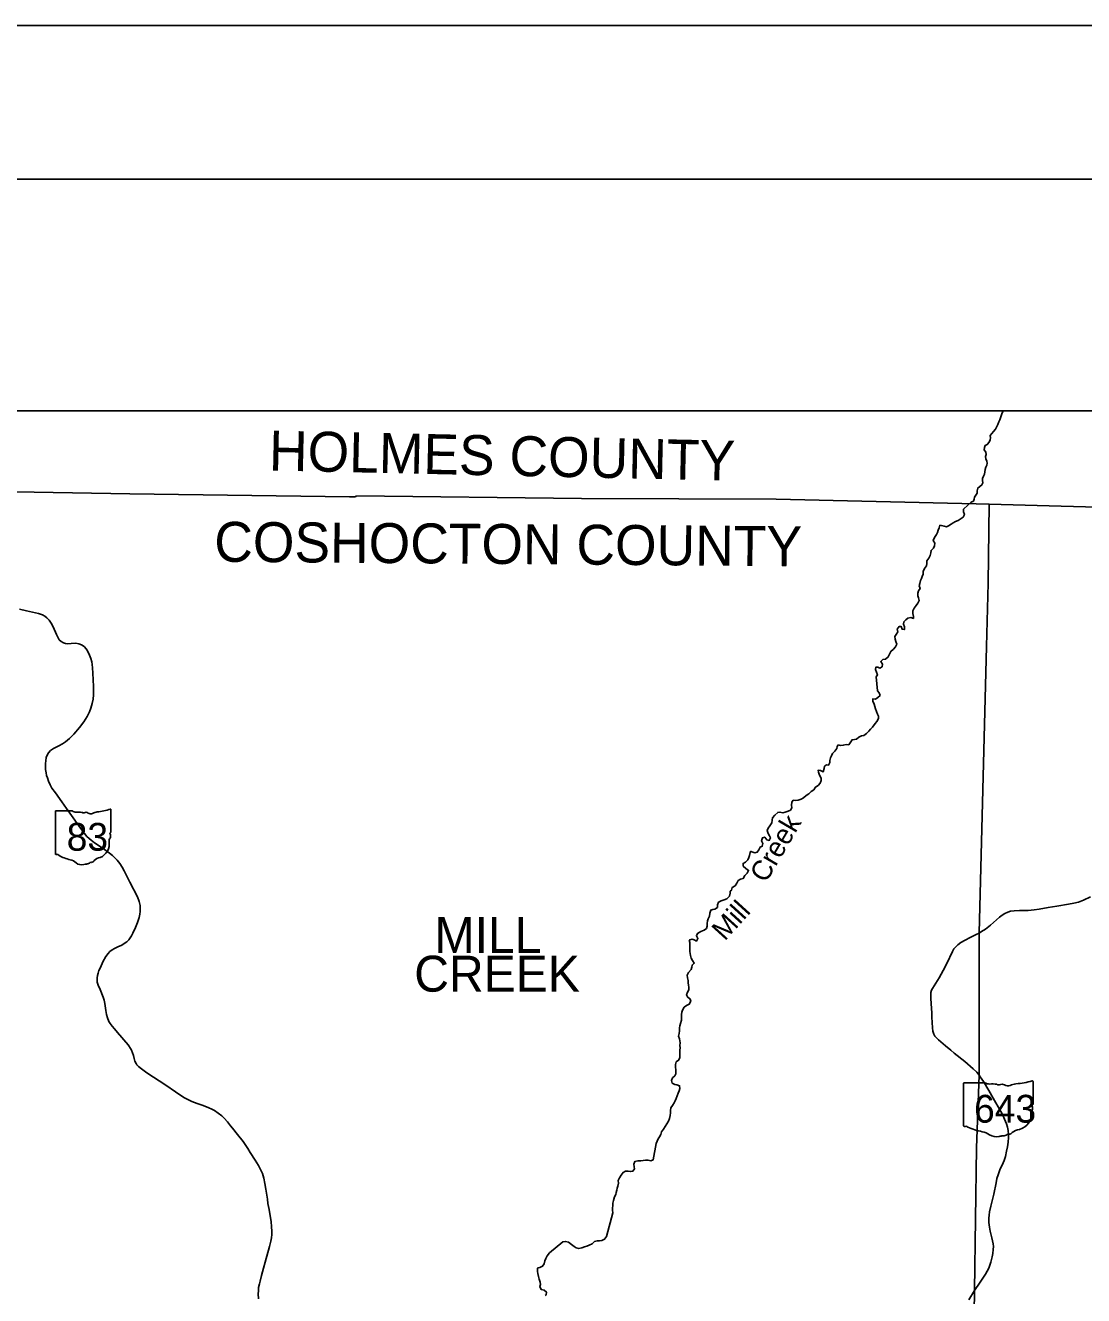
# Model space of a CAD drawing. Extents: x -6.3 to 34, y 0 to 22.
# Drawn here: x 5.581 to 9.018, y 17.873 to 22 of the extents above; entities that cross this region are included whole.
import ezdxf

# ---------------------------------------------------------------- set-up
doc = ezdxf.new("R2010")
doc.units = 0
for name, color, linetype in [('GM_X_County', 7, 'Continuous'), ('GM_X_County_Text', 7, 'Continuous'), ('GM_X_Minor_River', 7, 'Continuous'), ('GM_X_Minor_River_Text', 7, 'Continuous'), ('GM_X_State_Location', 7, 'Continuous'), ('GM_X_State_Route', 7, 'Continuous'), ('GM_X_State_Shield', 7, 'Continuous'), ('GM_X_Township', 7, 'Continuous'), ('GM_X_Township_Text', 7, 'Continuous'), ('SH_Border', 7, 'Continuous'), ('SH_Cut_Line', 7, 'Continuous'), ('SH_Text', 7, 'Continuous')]:
    doc.layers.add(name, color=color, linetype=linetype)

msp = doc.modelspace()

# ---------------------------------------------------------------- linework, layer by layer
at = {"layer": 'GM_X_County'}
for points in [[(5.4835, 20.4857), (5.92, 20.4781), (6.6339, 20.4679), (6.6359, 20.4682), (6.6378, 20.4682), (6.6401, 20.4681), (6.6424, 20.4681), (6.6467, 20.4681), (6.649, 20.4681), (6.6511, 20.4684), (6.6531, 20.4689), (6.6549, 20.4698), (6.6565, 20.4711), (7.387, 20.4633), (8.02, 20.4602), (8.6692, 20.445), (8.712, 20.4444)], [(8.712, 20.4444), (9.2192, 20.43)]]:
    msp.add_lwpolyline(points, dxfattribs=at)
at = {"layer": 'GM_X_Minor_River'}
for points in [[(8.6427, 20.4411), (8.6537, 20.4512), (8.6605, 20.454), (8.6633, 20.4605), (8.6636, 20.467), (8.6682, 20.4735), (8.6729, 20.4803), (8.6731, 20.4881), (8.6744, 20.4964), (8.6814, 20.5021), (8.6882, 20.5071), (8.6913, 20.5135), (8.6897, 20.5213), (8.6905, 20.5281), (8.6938, 20.5354), (8.6964, 20.5419), (8.6972, 20.5497), (8.6987, 20.5572), (8.7011, 20.5642), (8.7037, 20.5707), (8.7052, 20.5772), (8.7044, 20.5842), (8.7005, 20.5917), (8.7, 20.5993), (8.7023, 20.6058), (8.7008, 20.613), (8.6958, 20.6208), (8.6969, 20.6281), (8.6984, 20.6348), (8.7057, 20.6382), (8.7119, 20.6458), (8.7152, 20.6538), (8.7158, 20.6603), (8.7145, 20.6671), (8.7199, 20.6743), (8.7261, 20.6808), (8.7318, 20.6881), (8.7365, 20.6964), (8.7401, 20.7037), (8.7434, 20.7118), (8.7466, 20.7185), (8.7489, 20.725), (8.7502, 20.7318), (8.7528, 20.7383), (8.7561, 20.7455), (8.7583, 20.7482)], [(8.5514, 20.3766), (8.5568, 20.3748), (8.5657, 20.3728), (8.573, 20.3713), (8.58, 20.3739), (8.588, 20.3794), (8.595, 20.3839), (8.6025, 20.3881), (8.611, 20.3918), (8.6209, 20.3979), (8.6276, 20.4023), (8.6312, 20.4104), (8.6283, 20.419), (8.6287, 20.4284), (8.6427, 20.4411)], [(8.2214, 19.6628), (8.2289, 19.6601), (8.2374, 19.6612), (8.247, 19.6631), (8.2556, 19.6623), (8.2623, 19.6717), (8.2664, 19.6788), (8.274, 19.6799), (8.281, 19.6805), (8.2882, 19.687), (8.297, 19.6912), (8.3045, 19.6931), (8.3136, 19.6994), (8.3213, 19.7065), (8.3262, 19.713), (8.3322, 19.7196), (8.3412, 19.7313), (8.3463, 19.7381), (8.352, 19.7478), (8.3519, 19.7551), (8.349, 19.7616), (8.3454, 19.7702), (8.3424, 19.7795), (8.34, 19.7871), (8.3379, 19.7941), (8.3337, 19.804), (8.3336, 19.8118), (8.3425, 19.8108), (8.3497, 19.8163), (8.3572, 19.8224), (8.3548, 19.8315), (8.3491, 19.8382), (8.3446, 19.883), (8.3487, 19.8901), (8.3461, 19.8989), (8.3419, 19.9072), (8.3439, 19.9148), (8.3504, 19.9146), (8.3569, 19.912), (8.3639, 19.9159), (8.3654, 19.9243), (8.3594, 19.9334), (8.3663, 19.9402), (8.3754, 19.9408), (8.3839, 19.9481), (8.3875, 19.9575), (8.3924, 19.9661), (8.4009, 19.973), (8.4079, 19.9805), (8.4112, 19.9899), (8.4083, 19.9977), (8.4059, 20.0056), (8.4048, 20.0139), (8.4092, 20.0212), (8.4151, 20.0293), (8.413, 20.0379), (8.4189, 20.0468), (8.4259, 20.0466), (8.4288, 20.038), (8.4361, 20.0367), (8.4366, 20.0461), (8.4339, 20.055), (8.4344, 20.062), (8.4408, 20.0688), (8.4478, 20.0743), (8.4567, 20.0759), (8.4658, 20.0731), (8.4662, 20.0796), (8.4641, 20.0887), (8.464, 20.0976), (8.4684, 20.107), (8.4748, 20.1151), (8.4803, 20.1222), (8.4838, 20.1313), (8.4822, 20.1404), (8.4801, 20.1469), (8.4795, 20.1553), (8.4823, 20.1631), (8.487, 20.1704), (8.4848, 20.179), (8.4866, 20.1861), (8.4889, 20.196), (8.4914, 20.2025), (8.494, 20.2093), (8.4973, 20.2174), (8.4975, 20.226), (8.5019, 20.2354), (8.5078, 20.2438), (8.509, 20.2521), (8.5092, 20.2604), (8.5162, 20.2686), (8.5195, 20.2777), (8.5221, 20.2868), (8.523, 20.2941), (8.5311, 20.3015), (8.5344, 20.3088), (8.5351, 20.3179), (8.5299, 20.3265), (8.534, 20.3359), (8.5404, 20.3456), (8.5437, 20.3524)], [(8.5437, 20.3524), (8.5465, 20.3597), (8.5491, 20.3675), (8.5514, 20.3766)], [(8.0749, 19.4824), (8.0819, 19.4818), (8.0913, 19.4829), (8.1009, 19.4859), (8.1089, 19.4901), (8.1177, 19.4977), (8.1259, 19.5032), (8.1337, 19.5105), (8.1417, 19.5166), (8.1474, 19.5249), (8.1557, 19.5299), (8.1624, 19.538), (8.1654, 19.5469), (8.1662, 19.554), (8.1609, 19.5641), (8.1575, 19.5732), (8.1561, 19.58), (8.1637, 19.5787), (8.1728, 19.5748), (8.1761, 19.5853), (8.1766, 19.5926), (8.1833, 19.597), (8.1898, 19.5968), (8.1936, 19.6052), (8.1941, 19.612), (8.1959, 19.6198), (8.1992, 19.6263), (8.2028, 19.6344), (8.2108, 19.6423), (8.2165, 19.6509), (8.2177, 19.6574), (8.2214, 19.6628)], [(7.9367, 19.3165), (7.9409, 19.3151), (7.95, 19.3112), (7.9585, 19.3141), (7.9634, 19.3209), (7.968, 19.3301), (7.9748, 19.333), (7.9765, 19.3419), (7.9721, 19.3509), (7.9749, 19.3601), (7.9826, 19.3625), (7.9895, 19.3537), (7.9975, 19.3521), (8.0011, 19.36), (7.9982, 19.3665), (7.994, 19.3748), (7.9903, 19.3836), (7.9939, 19.392), (7.9993, 19.3993), (8.0057, 19.4087), (8.0072, 19.4176), (8.0082, 19.4257), (8.0154, 19.4338), (8.0247, 19.4427), (8.0317, 19.444), (8.0414, 19.4417), (8.0492, 19.4439), (8.059, 19.4468), (8.066, 19.45), (8.0709, 19.4575), (8.0693, 19.4669), (8.0708, 19.4758), (8.0749, 19.4824)], [(7.87, 19.1868), (7.8741, 19.1897), (7.8769, 19.199), (7.8862, 19.2043), (7.8922, 19.2132), (7.896, 19.2216), (7.9043, 19.2258), (7.9126, 19.2284), (7.9177, 19.2378), (7.9257, 19.2452), (7.9301, 19.2543), (7.9209, 19.261), (7.9128, 19.2686), (7.9123, 19.2769), (7.9198, 19.2816), (7.9275, 19.2892), (7.9311, 19.2963), (7.9326, 19.3028), (7.9357, 19.3124), (7.9367, 19.3165)], [(7.7366, 19.025), (7.739, 19.0284), (7.7471, 19.0311), (7.7536, 19.029), (7.7609, 19.0246), (7.7655, 19.0333), (7.7608, 19.0418), (7.7641, 19.0497), (7.7747, 19.056), (7.7856, 19.0602), (7.7931, 19.0662), (7.7956, 19.0728), (7.7958, 19.0814), (7.7968, 19.0905), (7.7986, 19.097), (7.8035, 19.1056), (7.8047, 19.1153), (7.807, 19.1247), (7.814, 19.1278), (7.8207, 19.1289), (7.8288, 19.1342), (7.8297, 19.143), (7.8328, 19.1509), (7.8413, 19.1556), (7.8509, 19.1585), (7.86, 19.1625), (7.8677, 19.1711), (7.87, 19.1805), (7.87, 19.1868)], [(7.7094, 18.7573), (7.7122, 18.768), (7.7121, 18.7771), (7.7118, 18.7865), (7.7128, 18.7938), (7.7156, 18.8006), (7.7213, 18.81), (7.7282, 18.8158), (7.7376, 18.8203), (7.7427, 18.8294), (7.7403, 18.8364), (7.7319, 18.8431), (7.7288, 18.8499), (7.7316, 18.8583), (7.7359, 18.8664), (7.7364, 18.875), (7.7353, 18.8815), (7.7337, 18.8887), (7.7337, 18.8971), (7.732, 18.9057), (7.7309, 18.914), (7.7353, 18.9226), (7.7433, 18.932), (7.7456, 18.9401), (7.7468, 18.9467), (7.7536, 18.9529), (7.748, 18.9613), (7.7436, 18.9698), (7.7417, 18.9781), (7.7404, 18.9847), (7.7395, 18.9912), (7.739, 18.9992), (7.7392, 19.0063), (7.7394, 19.0149), (7.7393, 19.0214), (7.7366, 19.025)], [(7.7068, 18.6706), (7.7078, 18.6779), (7.7073, 18.6851), (7.708, 18.6937), (7.7069, 18.7003), (7.7053, 18.707), (7.7029, 18.7161), (7.7042, 18.7247), (7.7054, 18.7336), (7.7056, 18.7424), (7.7063, 18.749), (7.7094, 18.7573)], [(7.5307, 18.2772), (7.5385, 18.2768), (7.5455, 18.2758), (7.5546, 18.2776), (7.5592, 18.2852), (7.5582, 18.2917), (7.5571, 18.3), (7.5604, 18.3081), (7.57, 18.3103), (7.5796, 18.3111), (7.5882, 18.3119), (7.5952, 18.313), (7.604, 18.3128), (7.6126, 18.3113), (7.6204, 18.3145), (7.6302, 18.3666), (7.633, 18.3745), (7.6366, 18.3818), (7.6407, 18.3883), (7.6448, 18.3964), (7.6473, 18.405), (7.6538, 18.4134), (7.6589, 18.4218), (7.6648, 18.4309), (7.67, 18.4393), (7.6733, 18.4479), (7.6755, 18.4581), (7.6768, 18.4662), (7.677, 18.4745), (7.678, 18.4826), (7.6826, 18.4907), (7.688, 18.499), (7.6921, 18.5056), (7.6954, 18.5137), (7.6985, 18.5218), (7.701, 18.5304), (7.7046, 18.5387), (7.7072, 18.5458), (7.7061, 18.5546), (7.6975, 18.5572), (7.6907, 18.559), (7.6818, 18.5636), (7.6795, 18.5722), (7.6825, 18.58), (7.6905, 18.5868), (7.6939, 18.5934), (7.6933, 18.6004), (7.6935, 18.6077), (7.6932, 18.6142), (7.6929, 18.6238), (7.6952, 18.6319), (7.7029, 18.6377), (7.7068, 18.645), (7.707, 18.6541), (7.7069, 18.6609), (7.7066, 18.669), (7.7068, 18.6706)], [(7.2455, 17.9629), (7.2522, 17.9643), (7.261, 17.9685), (7.2656, 17.9766), (7.2684, 17.9863), (7.272, 17.9936), (7.2761, 18.0022), (7.283, 18.0114), (7.3267, 18.0481), (7.3355, 18.0492), (7.3452, 18.0461), (7.3546, 18.0394), (7.3632, 18.0322), (7.3697, 18.0278), (7.3786, 18.0258), (7.3882, 18.0279), (7.397, 18.0316), (7.4048, 18.034), (7.4123, 18.0364), (7.4216, 18.0411), (7.4296, 18.0492), (7.4387, 18.0511), (7.4452, 18.0506), (7.4535, 18.052), (7.4626, 18.0562), (7.4685, 18.0646), (7.489, 18.1418), (7.4882, 18.1504), (7.4876, 18.1574), (7.4891, 18.1658), (7.4896, 18.1733), (7.4913, 18.1819), (7.4946, 18.1937), (7.4985, 18.201), (7.5003, 18.2078), (7.5018, 18.2151), (7.5033, 18.2221), (7.5051, 18.2286), (7.5071, 18.2383), (7.507, 18.2469), (7.5108, 18.2558), (7.5165, 18.2646), (7.5222, 18.2733), (7.5307, 18.2772)], [(7.2688, 17.8729), (7.2725, 17.8753), (7.2732, 17.8845), (7.2657, 17.8902), (7.2568, 17.8924), (7.2521, 17.9021), (7.2541, 17.9086), (7.2535, 17.9169), (7.2498, 17.9265), (7.2474, 17.9351), (7.245, 17.9442), (7.2442, 17.9507), (7.2449, 17.9599), (7.2455, 17.9629)]]:
    msp.add_lwpolyline(points, dxfattribs=at)
at = {"layer": 'GM_X_State_Route'}
for points in [[(5.8139, 18.899), (5.8141, 18.905), (5.8149, 18.9126), (5.8169, 18.9206), (5.8198, 18.9291), (5.8246, 18.9393), (5.8329, 18.9574), (5.8416, 18.9743), (5.8494, 18.9849), (5.8551, 18.9909), (5.8625, 18.9964), (5.8702, 19.0005), (5.8809, 19.0056), (5.8941, 19.012), (5.9021, 19.0167), (5.9104, 19.0227), (5.9166, 19.0288), (5.921, 19.0348), (5.9258, 19.0416), (5.9301, 19.0504), (5.9382, 19.0689), (5.9445, 19.0847), (5.9505, 19.1017), (5.9528, 19.1119), (5.9539, 19.1212), (5.9539, 19.1312), (5.9537, 19.1402), (5.9505, 19.1533), (5.9445, 19.169), (5.9203, 19.2166), (5.9018, 19.2525), (5.8952, 19.265), (5.8873, 19.2768), (5.8788, 19.2875), (5.8732, 19.2936), (5.8636, 19.3029), (5.8545, 19.31), (5.8332, 19.3254), (5.8056, 19.3438), (5.8, 19.3481), (5.7947, 19.3522), (5.7882, 19.3577), (5.7807, 19.365), (5.7725, 19.3744), (5.7596, 19.3917), (5.7254, 19.4403), (5.7144, 19.4559), (5.6987, 19.4777), (5.6782, 19.5063), (5.6672, 19.5221), (5.6608, 19.533), (5.6559, 19.5446), (5.6522, 19.5549), (5.6498, 19.5625), (5.6479, 19.5718), (5.6463, 19.5825), (5.6456, 19.5891), (5.6458, 19.6013), (5.6467, 19.6107), (5.6488, 19.6208), (5.6531, 19.6307), (5.6561, 19.6361), (5.6628, 19.6442), (5.6716, 19.6503), (5.6781, 19.654), (5.6891, 19.6591), (5.7018, 19.6657), (5.7116, 19.6726), (5.7239, 19.6827), (5.7387, 19.6973), (5.7571, 19.7192), (5.7703, 19.7367), (5.7816, 19.7544), (5.7893, 19.77), (5.7936, 19.7811), (5.7982, 19.7965), (5.8011, 19.8107), (5.8024, 19.8246), (5.8019, 19.8522), (5.8001, 19.8957), (5.7992, 19.9121), (5.7977, 19.923), (5.7961, 19.9324), (5.7933, 19.9431), (5.7893, 19.9539), (5.7829, 19.9676), (5.7783, 19.9743), (5.7714, 19.9818), (5.7627, 19.9876), (5.7539, 19.9911), (5.7445, 19.9927), (5.7295, 19.9912), (5.719, 19.9904), (5.7115, 19.9912), (5.7048, 19.9935), (5.6971, 19.9981), (5.6909, 20.0038), (5.6869, 20.0102), (5.682, 20.0207), (5.6708, 20.0459), (5.6647, 20.058), (5.658, 20.0678), (5.6504, 20.0756), (5.6438, 20.0805), (5.6364, 20.0848), (5.6236, 20.0891), (5.5839, 20.0982), (5.5616, 20.1033)], [(8.6103, 19.0124), (8.6199, 19.0198), (8.6333, 19.0279), (8.6497, 19.0368), (8.6693, 19.0462), (8.6793, 19.051), (8.6872, 19.0554), (8.6994, 19.0636), (8.7156, 19.0764), (8.7448, 19.1024), (8.7539, 19.1093), (8.7625, 19.1148), (8.7718, 19.119), (8.7809, 19.1218), (8.7924, 19.1234), (8.8104, 19.1239), (8.8388, 19.1245), (8.8582, 19.1263), (8.8746, 19.1286), (8.9036, 19.1341), (8.9318, 19.1385), (8.9689, 19.1445), (8.9862, 19.1477), (9.002, 19.1514), (9.0182, 19.1576), (9.0413, 19.1689)], [(8.532, 18.7228), (8.529, 18.7317), (8.5274, 18.7424), (8.5258, 18.7775), (8.525, 18.7917), (8.5243, 18.8059), (8.522, 18.8386), (8.5217, 18.8508), (8.5227, 18.8578), (8.5248, 18.8649), (8.5278, 18.871), (8.5489, 18.9055), (8.5623, 18.9292), (8.5737, 18.952), (8.5923, 18.9914), (8.5972, 18.9993), (8.6039, 19.0064), (8.6103, 19.0124)], [(5.925, 18.6706), (5.924, 18.673), (5.9147, 18.6879), (5.8801, 18.7277), (5.87, 18.7392), (5.8622, 18.7485), (5.8564, 18.7568), (5.8521, 18.7638), (5.8471, 18.7754), (5.8441, 18.7864), (5.8419, 18.7992), (5.8384, 18.8225), (5.8368, 18.8326), (5.8339, 18.8426), (5.8233, 18.8672), (5.8171, 18.8818), (5.8142, 18.8914), (5.8139, 18.899)], [(8.5871, 18.6706), (8.5699, 18.6849), (8.5466, 18.7044), (8.5395, 18.7113), (8.5355, 18.7162), (8.532, 18.7228)], [(6.3383, 17.8622), (6.3375, 17.8788), (6.3378, 17.8883), (6.3386, 17.899), (6.3411, 17.9116), (6.3433, 17.9203), (6.3482, 17.9378), (6.3546, 17.9616), (6.3601, 17.9817), (6.3742, 18.0328), (6.378, 18.0502), (6.3799, 18.0603), (6.3812, 18.0711), (6.3816, 18.0811), (6.3807, 18.0972), (6.3789, 18.1131), (6.3724, 18.1523), (6.3689, 18.1716), (6.3669, 18.1858), (6.3615, 18.2186), (6.3585, 18.2374), (6.355, 18.2546), (6.3506, 18.2693), (6.3458, 18.2808), (6.3382, 18.2955), (6.3272, 18.3132), (6.3115, 18.3378), (6.3034, 18.3508), (6.288, 18.3736), (6.2697, 18.3966), (6.2538, 18.4164), (6.2476, 18.4246), (6.2374, 18.4371), (6.227, 18.449), (6.2188, 18.4567), (6.2075, 18.4658), (6.195, 18.4741), (6.187, 18.4784), (6.1768, 18.4832), (6.1583, 18.4903), (6.1388, 18.4969), (6.1217, 18.5032), (6.1107, 18.5085), (6.096, 18.517), (6.0686, 18.5352), (6.0375, 18.5563), (5.9758, 18.5972), (5.9576, 18.6095), (5.9483, 18.617), (5.9429, 18.6229), (5.9405, 18.6266), (5.9366, 18.6342), (5.9337, 18.6436), (5.9317, 18.6531), (5.9289, 18.6614), (5.925, 18.6706)], [(8.6458, 17.8596), (8.6642, 17.8894), (8.6681, 17.8955), (8.6779, 17.9097), (8.6893, 17.9264), (8.6997, 17.9423), (8.7056, 17.9523), (8.7101, 17.9616), (8.717, 17.9811), (8.7216, 17.9988), (8.7238, 18.01), (8.7252, 18.0226), (8.7253, 18.0326), (8.7244, 18.0406), (8.7227, 18.0505), (8.7204, 18.0604), (8.7154, 18.0821), (8.7128, 18.0953), (8.7111, 18.1106), (8.7111, 18.1241), (8.7115, 18.1346), (8.7132, 18.1447), (8.7175, 18.1636), (8.7265, 18.2025), (8.7341, 18.2394), (8.737, 18.2535), (8.7404, 18.2655), (8.7438, 18.2754), (8.7476, 18.2843), (8.7536, 18.2963), (8.7607, 18.312), (8.7647, 18.3247), (8.7681, 18.3419), (8.771, 18.3566), (8.7731, 18.3717), (8.7746, 18.387), (8.7744, 18.3968), (8.7734, 18.4089), (8.771, 18.4205), (8.7676, 18.4315), (8.7617, 18.4465), (8.7558, 18.4588), (8.7491, 18.4712), (8.7245, 18.514), (8.7102, 18.5394), (8.6932, 18.5681), (8.6829, 18.584), (8.6792, 18.5892), (8.6714, 18.599), (8.6601, 18.6097), (8.6325, 18.6335), (8.5985, 18.6611), (8.5871, 18.6706)]]:
    msp.add_lwpolyline(points, dxfattribs=at)
at = {"layer": 'GM_X_State_Shield'}
for p, q in [((5.6782, 19.4459), (5.6782, 19.3087)), ((5.7329, 19.4482), (5.68, 19.4482)), ((5.8589, 19.3799), (5.8589, 19.4516)), ((5.8589, 19.3799), (5.8589, 19.3799)), ((8.6288, 18.5622), (8.6288, 18.4251)), ((8.6971, 18.5646), (8.631, 18.5646)), ((8.8546, 18.4963), (8.8546, 18.568)), ((8.8546, 18.4963), (8.8546, 18.4963))]:
    msp.add_line(p, q, dxfattribs=at)
for centre, radius, start, end in [((5.6803, 19.4462), 0.00209, 98.1301, 188.1301), ((5.7455, 19.4642), 0.0203, 231.6195, 271.1119), ((5.7523, 19.3712), 0.0729, 80.4867, 94.9883), ((5.7688, 19.4469), 0.00586, 219.7921, 297.1024), ((5.7774, 19.431), 0.0122, 54.4667, 119.1411), ((5.7931, 19.4528), 0.0147, 233.8562, 294.8282), ((5.819, 19.4063), 0.0386, 97.3462, 120.7689), ((5.7946, 19.6352), 0.1916, 275.8445, 288.9065), ((5.8569, 19.4519), 0.00201, 351.8621, 97.738), ((5.8661, 19.3499), 0.0136, 136.8065, 186.9296), ((5.8585, 19.3746), 0.00311, 107.944, 210.337), ((5.8387, 19.3656), 0.0187, 340.033, 23.6496), ((5.8568, 19.3796), 0.00215, 289.6038, 7.7341), ((5.8053, 19.3407), 0.0479, 292.3089, 8.9858), ((5.6803, 19.3084), 0.00211, 171.9584, 258.3066), ((5.6806, 19.3225), 0.0161, 267.339, 280.6039), ((5.6839, 19.3008), 0.00581, 29.7484, 93.2717), ((5.7573, 19.424), 0.1384, 240.4129, 257.1985), ((5.716, 19.2471), 0.0433, 47.1842, 75.836), ((5.7629, 19.3001), 0.0275, 230.7004, 286.2918), ((5.7787, 19.2527), 0.0226, 85.6951, 111.2099), ((5.7808, 19.2899), 0.0146, 268.777, 315.5493), ((5.794, 19.2766), 0.00412, 65.7517, 132.6484), ((5.7922, 19.2954), 0.0155, 282.8732, 323.2771), ((5.8255, 19.2702), 0.0263, 94.4031, 142.5768)]:
    msp.add_arc(centre, radius, start, end, dxfattribs=at)
for centre, major_axis, start_param, end_param in [((8.6313, 18.5625), (0.00262, 0), 1.712693, 3.28349), ((8.7129, 18.5805), (0.0254, 0), 4.042523, 4.731795), ((8.7213, 18.4876), (0.0911, 0), 1.404758, 1.657858), ((8.742, 18.5632), (0.00732, 0), 3.836095, 5.185415), ((8.7527, 18.5474), (0.0152, 0), 0.950623, 2.079405), ((8.7724, 18.5691), (0.0183, 0), 4.081561, 5.145723), ((8.8047, 18.5227), (0.0482, 0), 1.699011, 2.107814), ((8.7742, 18.7516), (0.2395, 0), 4.814394, 5.042369), ((8.8521, 18.5683), (0.00251, 0), 6.141152, 7.989035), ((8.8541, 18.491), (0.00389, 0), 1.883978, 3.671073), ((8.8293, 18.4819), (0.0234, 0), 5.934695, 6.695948), ((8.852, 18.496), (0.00269, 0), 5.05454, 6.418171), ((8.7876, 18.4571), (0.0599, 0), 5.101752, 6.440018), ((8.8636, 18.4662), (0.017, 0), 2.387724, 3.262537), ((8.6314, 18.4248), (0.00264, 0), 3.00124, 4.508301), ((8.6318, 18.4388), (0.0201, 0), 4.665946, 4.897461), ((8.6359, 18.4172), (0.00726, 0), 0.519207, 1.627899), ((8.7276, 18.5404), (0.173, 0), 4.195997, 4.488961), ((8.8129, 18.3866), (0.0328, 0), 1.647645, 2.488434), ((8.676, 18.3635), (0.0541, 0), 0.823519, 1.323587), ((8.7346, 18.4165), (0.0343, 0), 4.026481, 4.996735), ((8.7544, 18.3691), (0.0282, 0), 1.495662, 1.94098), ((8.7569, 18.4062), (0.0183, 0), 4.691044, 5.507374), ((8.7735, 18.3929), (0.00515, 0), 1.147584, 2.315152), ((8.7713, 18.4118), (0.0194, 0), 4.937069, 5.64225)]:
    msp.add_ellipse(centre, major_axis=major_axis, ratio=0.8, start_param=start_param, end_param=end_param, dxfattribs=at)
at = {"layer": 'GM_X_Township'}
msp.add_lwpolyline([(8.712, 20.4444), (8.7081, 20.1879), (8.7029, 19.9815), (8.6792, 19.0514), (8.6791, 18.5896), (8.6708, 18.3533), (8.664, 17.8898), (8.6619, 17.7454), (8.6569, 17.6641), (8.6519, 17.32), (8.6486, 17.1596), (8.6445, 16.9602), (7.7616, 16.9856), (6.9974, 17.0077), (6.3091, 17.0275), (5.744, 17.0438), (5.416, 17.0563)], dxfattribs=at)
at = {"layer": 'SH_Border'}
msp.add_lwpolyline([(1.5, 21.5), (33.5, 21.5), (33.5, 0.5), (1.5, 0.5)], close=True, dxfattribs=at)
at = {"layer": 'SH_Cut_Line'}
msp.add_lwpolyline([(0, 0), (34, 0), (34, 22), (0, 22)], close=True, dxfattribs=at)
at = {"layer": 'SH_Text'}
msp.add_lwpolyline([(1.8145, 20.7482), (12.189, 20.7482), (12.189, 9.3884), (1.8145, 9.3884)], close=True, dxfattribs=at)

# ---------------------------------------------------------------- texts
at = {"layer": 'GM_X_County_Text'}
for s, rotation, p in [('HOLMES COUNTY', 358.7329, (6.3711, 20.554)), ('COSHOCTON COUNTY', 359.5483, (6.194, 20.2575))]:
    msp.add_text(s, height=0.129798, rotation=rotation, dxfattribs=at).set_placement(p)
at = {"layer": 'GM_X_Minor_River_Text'}
for s, rotation, p in [('Creek', 59.5929, (7.9864, 19.2108)), ('Mill', 47.7745, (7.8527, 19.0231))]:
    msp.add_text(s, height=0.0649, rotation=rotation, dxfattribs=at).set_placement(p)
at = {"layer": 'GM_X_State_Location'}
for s, p in [('83', (5.7339, 19.3587)), ('643', (8.7151, 18.4769))]:
    msp.add_text(s, height=0.00013, rotation=0, dxfattribs=at).set_placement(p)
for s, p in [('s', (5.7665, 19.3682)), ('r', (5.7665, 19.3682)), ('s', (8.7609, 18.4864)), ('r', (8.7609, 18.4864))]:
    msp.add_text(s, height=0.00013, dxfattribs=at).set_placement(p)
at = {"layer": 'GM_X_State_Shield'}
for s, p in [('83', (5.715, 19.3184)), ('643', (8.6627, 18.4348))]:
    msp.add_text(s, height=0.09035, dxfattribs=at).set_placement(p)
at = {"layer": 'GM_X_Township_Text'}
for s, p in [('MILL', (6.9099, 18.9861)), ('CREEK', (6.844, 18.8604))]:
    msp.add_text(s, height=0.11682, rotation=0, dxfattribs=at).set_placement(p)

doc.saveas('drawing.dxf')
